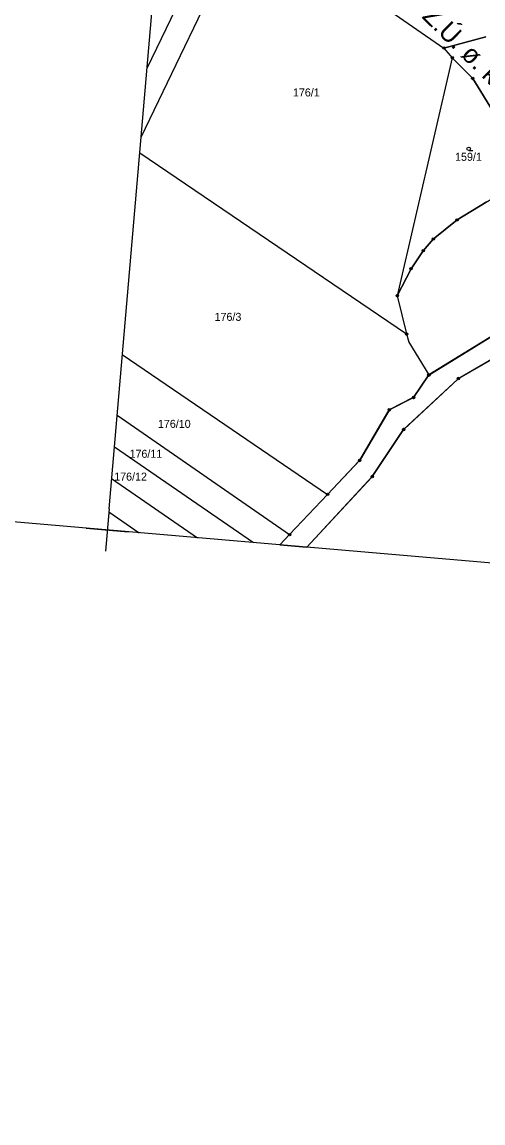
# Model space of a CAD drawing. Extents: x -537341 to -532984, y -1143469 to -1141314.
# Drawn here: x -536112 to -535916.1, y -1143459.1 to -1142991.3 of the extents above; entities that cross this region are included whole.
import ezdxf

# ---------------------------------------------------------------- set-up
doc = ezdxf.new("R2010")
doc.units = 0
for name, color, linetype in [('Hranice parcel', 7, 'Continuous'), ('parcelní_č_2000', 7, 'Continuous'), ('Polygon ku', 7, 'Continuous'), ('u_arcibiskupství', 7, 'Continuous'), ('u_km_popis', 7, 'Continuous'), ('u_obec_Horní_Moš', 7, 'Continuous'), ('u_obec_Věžky', 7, 'Continuous'), ('u_povodí', 7, 'Continuous'), ('x_formát_křížky', 7, 'Continuous'), ('x_formát_rám', 7, 'Continuous'), ('Značky bodu BP', 7, 'Continuous'), ('Značky kultur', 7, 'Continuous')]:
    doc.layers.add(name, color=color, linetype=linetype)

# ---------------------------------------------------------------- blocks, each defined once
blk = doc.blocks.new('BIG')
at = {"layer": 'x_formát_křížky'}
for p, q in [((-1470, 4.5), (-1470, -4.5)), ((-1474.5, 0), (-1465.5, 0))]:
    blk.add_line(p, q, dxfattribs=at)
at = {"layer": 'x_formát_rám'}
blk.add_line((0, 0), (-2100, 0), dxfattribs=at)

msp = doc.modelspace()

# ---------------------------------------------------------------- linework, layer by layer
at = {"layer": 'Hranice parcel'}
for p, q in [((-535932.72, -1143002.31), (-535914.94, -1142997.59)), ((-535932.72, -1143002.31), (-535929.2, -1143006.47)), ((-535929.2, -1143006.47), (-535952.58, -1143107.56)), ((-536062.01, -1143046.84), (-535948.59, -1143123.78)), ((-535952.58, -1143107.56), (-535948.59, -1143123.78)), ((-535909.07, -1143122.84), (-535939.15, -1143141.25)), ((-535909.07, -1143122.84), (-535939.15, -1143141.25)), ((-536069.38, -1143132.51), (-535982.17, -1143191.97)), ((-536071.6, -1143158.37), (-535998.29, -1143209.04)), ((-536072.76, -1143171.82), (-536013.7, -1143212.44)), ((-536073.92, -1143185.3), (-536037.4, -1143210.4)), ((-535982.17, -1143191.97), (-535998.29, -1143209.04)), ((-535982.17, -1143191.97), (-535998.29, -1143209.04)), ((-536075.13, -1143199.37), (-536062.24, -1143208.26)), ((-535998.29, -1143209.04), (-536002.41, -1143213.41)), ((-535998.29, -1143209.04), (-536002.41, -1143213.41))]:
    msp.add_line(p, q, dxfattribs=at)
for points in [[(-536022.55, -1142935.45), (-536058.93, -1143011.03)], [(-536061.44, -1143040.21), (-536020.39, -1142955.06), (-536017.23, -1142951.65), (-536011.39, -1142949.86), (-536006.73, -1142951.11), (-535932.72, -1143002.31)], [(-535900.56, -1143038.04), (-535910.93, -1143030.73), (-535920.5, -1143015.26), (-535929.2, -1143006.47)], [(-535952.58, -1143107.56), (-535946.66, -1143096.1), (-535941.51, -1143088.44), (-535937.25, -1143083.52), (-535927.15, -1143075.34), (-535914.73, -1143067.85), (-535901.53, -1143060.74), (-535898.41, -1143052.4), (-535903.18, -1143039.88), (-535900.56, -1143038.04)], [(-535948.59, -1143123.78), (-535947.59, -1143127.26), (-535939.15, -1143141.25)], [(-535900.37, -1143127.62), (-535926.63, -1143142.85), (-535949.86, -1143164.43), (-535963.16, -1143184.45), (-535991.05, -1143214.39)], [(-535939.15, -1143141.25), (-535945.61, -1143150.78), (-535955.95, -1143156.01), (-535968.48, -1143177.46), (-535982.17, -1143191.97)], [(-535939.15, -1143141.25), (-535945.61, -1143150.78), (-535955.95, -1143156.01), (-535968.48, -1143177.46), (-535982.17, -1143191.97)]]:
    msp.add_lwpolyline(points, dxfattribs=at)
at = {"layer": 'Polygon ku'}
for points in [[(-535545.85, -1142885.6), (-535568.55, -1142894.7), (-535602.01, -1142916), (-535638.74, -1142928.55), (-535681.52, -1142942.46), (-535694.73, -1142949.04), (-535790.5, -1143003.05), (-535835.86, -1143036.82), (-535841.23, -1143042.93), (-535849.45, -1143049.16), (-535857.05, -1143051.75), (-535864.85, -1143060.59), (-535871.62, -1143083.23), (-535893.17, -1143112.23), (-535909.07, -1143122.84), (-535939.15, -1143141.25), (-535945.61, -1143150.78), (-535955.95, -1143156.01), (-535968.48, -1143177.46), (-535982.17, -1143191.97), (-535998.29, -1143209.04), (-536002.41, -1143213.41)], [(-536002.41, -1143213.41), (-535998.29, -1143209.04), (-535982.17, -1143191.97), (-535968.48, -1143177.46), (-535955.95, -1143156.01), (-535945.61, -1143150.78), (-535939.15, -1143141.25), (-535909.07, -1143122.84), (-535893.17, -1143112.23), (-535871.62, -1143083.23), (-535864.85, -1143060.59), (-535857.05, -1143051.75), (-535849.45, -1143049.16), (-535841.23, -1143042.93), (-535835.86, -1143036.82), (-535790.5, -1143003.05), (-535694.73, -1142949.04), (-535681.52, -1142942.46), (-535638.74, -1142928.55), (-535602.01, -1142916), (-535568.55, -1142894.7), (-535545.85, -1142885.6)]]:
    msp.add_lwpolyline(points, dxfattribs=at)
at = {"layer": 'u_arcibiskupství'}
msp.add_line((-535952.58, -1143107.56), (-535948.59, -1143123.78), dxfattribs=at)
for points in [[(-535900.56, -1143038.04), (-535903.18, -1143039.88), (-535898.41, -1143052.4), (-535901.53, -1143060.74), (-535914.73, -1143067.85), (-535927.15, -1143075.34), (-535937.25, -1143083.52), (-535941.51, -1143088.44), (-535946.66, -1143096.1), (-535952.58, -1143107.56)], [(-535948.59, -1143123.78), (-535947.59, -1143127.26), (-535939.15, -1143141.25)], [(-535939.15, -1143141.25), (-535938.72, -1143140.99), (-535909.5, -1143123.1)]]:
    msp.add_lwpolyline(points, dxfattribs=at)
at = {"layer": 'u_obec_Horní_Moš'}
for p, q in [((-535909.5, -1143123.1), (-535938.72, -1143140.99)), ((-535926.2, -1143142.6), (-535900.8, -1143127.87)), ((-535939.43, -1143141.66), (-535945.33, -1143150.37)), ((-535949.49, -1143164.09), (-535927, -1143143.19)), ((-535946.06, -1143151.01), (-535955.5, -1143155.78)), ((-535956.2, -1143156.44), (-535968.23, -1143177.03)), ((-535962.88, -1143184.03), (-535950.14, -1143164.85)), ((-535968.82, -1143177.82), (-535982.17, -1143191.97)), ((-535991.05, -1143214.39), (-535963.5, -1143184.82)), ((-535982.17, -1143191.97), (-535998.29, -1143209.04))]:
    msp.add_line(p, q, dxfattribs=at)
for points in [[(-535998.29, -1143209.04), (-536002.41, -1143213.41)], [(-536002.41, -1143213.41), (-535991.05, -1143214.39)]]:
    msp.add_lwpolyline(points, dxfattribs=at)
for centre, start, end in [((-535939.15, -1143141.25), 235.876, 31.4563), ((-535926.63, -1143142.85), 30.1005, 222.9013), ((-535945.61, -1143150.78), 206.8427, 55.8605), ((-535955.95, -1143156.01), 239.7157, 26.8181), ((-535949.86, -1143164.43), 42.8811, 236.4101), ((-535968.48, -1143177.46), 226.675, 59.7017), ((-535963.16, -1143184.45), 56.3949, 227.0335)]:
    msp.add_arc(centre, 0.5, start, end, dxfattribs=at)
at = {"layer": 'u_obec_Věžky'}
for p, q in [((-535914.94, -1142997.59), (-535932.72, -1143002.31)), ((-535932.72, -1143002.31), (-535929.2, -1143006.47))]:
    msp.add_line(p, q, dxfattribs=at)
msp.add_lwpolyline([(-535929.2, -1143006.47), (-535920.5, -1143015.26), (-535910.93, -1143030.73), (-535900.56, -1143038.04)], dxfattribs=at)
at = {"layer": 'x_formát_rám'}
msp.add_line((-536075.03, -1143198.13), (-536024.88, -1142615.28), dxfattribs=at)
at = {"layer": 'Značky bodu BP'}
for centre, radius in [((-535932.72, -1143002.31), 0.5), ((-535932.72, -1143002.31), 0.0303), ((-535929.2, -1143006.47), 0.5), ((-535929.2, -1143006.47), 0.0303), ((-535920.5, -1143015.26), 0.5), ((-535920.5, -1143015.26), 0.0303), ((-535927.15, -1143075.34), 0.5), ((-535927.15, -1143075.34), 0.0303), ((-535937.25, -1143083.52), 0.5), ((-535937.25, -1143083.52), 0.0303), ((-535941.51, -1143088.44), 0.5), ((-535941.51, -1143088.44), 0.0303), ((-535946.66, -1143096.1), 0.5), ((-535946.66, -1143096.1), 0.0303), ((-535952.58, -1143107.56), 0.5), ((-535952.58, -1143107.56), 0.0303), ((-535948.59, -1143123.78), 0.5), ((-535948.59, -1143123.78), 0.0303), ((-535939.15, -1143141.25), 0.5), ((-535939.15, -1143141.25), 0.0303), ((-535926.63, -1143142.85), 0.5), ((-535926.63, -1143142.85), 0.0303), ((-535945.61, -1143150.78), 0.5), ((-535945.61, -1143150.78), 0.0303), ((-535955.95, -1143156.01), 0.5), ((-535955.95, -1143156.01), 0.0303), ((-535949.86, -1143164.43), 0.5), ((-535949.86, -1143164.43), 0.0303), ((-535968.48, -1143177.46), 0.5), ((-535968.48, -1143177.46), 0.0303), ((-535963.16, -1143184.45), 0.5), ((-535963.16, -1143184.45), 0.0303), ((-535982.17, -1143191.97), 0.5), ((-535982.17, -1143191.97), 0.0303), ((-535998.29, -1143209.04), 0.5), ((-535998.29, -1143209.04), 0.0303)]:
    msp.add_circle(centre, radius, dxfattribs=at)
at = {"layer": 'Značky kultur'}
msp.add_line((-535922.19, -1143045.9), (-535920.44, -1143045.9), dxfattribs=at)
msp.add_circle((-535922.19, -1143045.15), 0.75, dxfattribs=at)

# ---------------------------------------------------------------- block references
at = {"layer": 'u_povodí', "xscale": 2.0000000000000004, "yscale": 1.9999999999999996, "rotation": -4.9171773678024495}
msp.add_blockref('BIG', (-533146.62, -1143459.1), dxfattribs=at)

# ---------------------------------------------------------------- texts
at = {"layer": 'parcelní_č_2000'}
for s, p in [('176/1', (-535996.89, -1143022.9)), ('159/1', (-535928, -1143050.23)), ('176/3', (-536030.18, -1143118.24)), ('176/10', (-536054.25, -1143163.71)), ('176/11', (-536066.32, -1143176.43)), ('176/12', (-536072.83, -1143186.14))]:
    msp.add_text(s, height=3.4, dxfattribs=at).set_placement(p)
at = {"layer": 'u_km_popis'}
msp.add_text('Z.Ú. ø. km 9,132', height=8, rotation=315.2894, dxfattribs=at).set_placement((-535942.39, -1142989.25))

doc.saveas('drawing.dxf')
